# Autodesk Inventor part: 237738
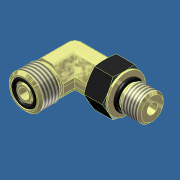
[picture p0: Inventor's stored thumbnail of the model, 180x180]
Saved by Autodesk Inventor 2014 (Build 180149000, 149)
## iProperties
Shininess: 20.0
Length Units: 11272
Angle Units: 11279
Time Units: 11290
Mass Units: 11286
Length Display Precision: 3
Angle Display Precision: 2
Company: Autodesk, Inc.
Created: 2002-05
Part Number: 237738
Material: Stainless Steel 316
Description: FITTING; EL-C9G12-(SS)
Document SubType Name: Modeling
Designer: Autodesk, Inc.
Density: 8.182 g/cm^3
Mass: 430.23 g
Surface Area: 171.066 cm^2
Volume: 52.5824 cm^3
Appearance: Stainless Steel
Density: 0.0
Volumn: 0.0
Area: 0.0
PropertySet Name: Model Information
Control State: 0
Master: False
Checked Out: True
Last Check In By: JT
Last Check In Date: 2003-06-20
Title: FITTING; EL-C9G12-(SS)
Author: Autodesk, Inc.
Comments: -
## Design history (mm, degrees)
derived "EL-C9G.ipt"
body "Solid1"
tag "TaggingFeature2"
feature "Solid1::EL-C9G.ipt" dims "ScaleForDerivedMember" = 10
